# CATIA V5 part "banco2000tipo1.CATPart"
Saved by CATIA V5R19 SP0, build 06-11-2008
Part number: banco2000tipo1
Material "Pine": density 500 kg/m3, Young's modulus 1.7e+10 Pa, Poisson ratio 0.45, thermal expansion 3.75e-06 1/K
Bounding box of the stored display mesh (mm): x -1000 to 1000, y -375 to 375, z -880 to 40
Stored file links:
  C:\Users\Fran Robles\Desktop\Clase de Catia\banco2000tipo1.CATPart
  C:\Program Files\Dassault Systemes\B19\win_b64\startup\materials\Catalog.CATMaterial
  C:\Program Files\Dassault Systemes\B19\win_b64\startup\materials\pinetree.jpg
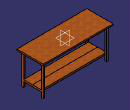
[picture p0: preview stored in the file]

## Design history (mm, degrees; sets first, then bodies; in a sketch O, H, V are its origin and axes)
Parameters
  Longitud_encimera = 2000 mm
  Ancho_encimera = 750 mm
  Altura_banco = 920 mm
  Altura_bandeja = 140 mm
  Altura_bandeja_porcentual_altura_banco = 0.25
Body1 (main body), material "Pine"
  Sketch1 "Encimera" on xy-plane, origin (0, 0, 0), H (1, 0, 0), V (0, 1, 0)
    line L1 (1000, 375) -> (1000, -375)
    line L2 (1000, -375) -> (-1000, -375)
    line L3 (-1000, -375) -> (-1000, 375)
    line L4 (-1000, 375) -> (1000, 375)
    length L2 = 2000 {= Longitud_encimera}
    length L1 = 750 {= Ancho_encimera}
    vertical: L1 V, L3 V
    horizontal: L2 H, L4 H
    equidistance: L1 L3 O, L2 L4 O
  Pad1: profile Sketch1, direction (0, 0, 1), length 40
  Sketch2 "Soporte de encimera" on start face of Pad1, origin (0, 0, 0), H (1, 0, 0), V (0, -1, 0)
    line L1 (930, 305) -> (930, -305)
    line L2 (930, -305) -> (-930, -305)
    line L3 (-930, -305) -> (-930, 305)
    line L4 (-930, 305) -> (930, 305)
    reference projected line E1 (-1000, 375) -> (1000, 375) from edge [start face of Pad1 | face of Pad1 from Sketch1.L2]
    reference projected line E2 (1000, 375) -> (1000, -375) from edge [start face of Pad1 | face of Pad1 from Sketch1.L1]
    line L5 (890, 265) -> (890, -265)
    line L6 (890, -265) -> (-890, -265)
    line L7 (-890, -265) -> (-890, 265)
    line L8 (-890, 265) -> (890, 265)
    distance E1 L4 = 70
    distance L1 E2 = 70
    distance L8 L4 = 40
    distance L5 L1 = 40
    vertical: L1 V, L3 V, L5 V, L7 V
    horizontal: L2 H, L4 H, L6 H, L8 H
    equidistance: L1 L3 O, L2 L4 O, L5 L7 O, L6 L8 O
  Pad2: profile Sketch2, direction (0, 0, -1), length 50
  Sketch3 "Pie de banco" on face of Pad2 from Sketch2.L3, origin (-930, 0, 0), H (0, -1, 0), V (0, 0, 1)
    reference projected line E1 (-375, 40) -> (375, 40) from edge [face of Pad1 from Sketch1.L3 | end face of Pad1]
    reference projected line E2 (305, -50) -> (-305, -50) from edge [face of Pad2 from Sketch2.L3 | end face of Pad2]
    point P3 (305, -50)
    line L1 (305, -50) -> (305, -880)
    point P5 (305, -880)
    line L2 (305, -880) -> (255, -880)
    point P6 (255, -880)
    line L3 (255, -880) -> (255, -740)
    point P7 (255, -740)
    line L4 (255, -740) -> (0, -740)
    point P8 (0, -740)
    construction line L5 (0, -740) -> (0, -690)
    point P9 (0, -690)
    line L6 (0, -690) -> (255, -690)
    point P10 (255, -690)
    line L7 (255, -690) -> (255, -50)
    point P11 (255, -50)
    line L8 (255, -50) -> (305, -50)
    point P12 (-255, -50)
    point P13 (-255, -690)
    line L9 (-255, -690) -> (-255, -50)
    point P14 (-305, -50)
    line L10 (-255, -50) -> (-305, -50)
    point P15 (-305, -880)
    line L11 (-305, -50) -> (-305, -880)
    point P16 (-255, -880)
    line L12 (-305, -880) -> (-255, -880)
    point P17 (-255, -740)
    line L13 (-255, -880) -> (-255, -740)
    point P18 (0, -740)
    line L14 (-255, -740) -> (0, -740)
    point P19 (0, -690)
    line L15 (0, -690) -> (-255, -690)
    distance L2 E1 = 920 {= Altura_banco}
    distance L3 L1 = 50
    distance L4 L6 = 50
    distance L2 L4 = 140 {= Altura_bandeja}
    vertical: L1 V, L3 V, L5 V, L7 V
    horizontal: L2 H, L4 H, L6 H, L8 H
    coincidence: P8 V, P10 L3, P11 E2, P8 P18, P9 P19
    symmetry: P11 P12 V, P10 P13 V, L7 L9 V, P3 P14 V, L8 L10 V, P5 P15 V, L1 L11 V, P6 P16 V, L2 L12 V, P7 P17 V, L3 L13 V, P8 P18 V, L4 L14 V, P9 P19 V, L6 L15 V
  Pad3: profile Sketch3, direction (1, 0, 0), length 40
  Mirror1: of Pad3, about yz-plane
  Sketch4 "Bandeja" on face of Pad3, origin (-890, 0, 0), H (0, 1, 0), V (0, 0, 1)
    line L1 (0, -740) -> (255, -740)
    line L2 (255, -740) -> (255, -690)
    line L3 (255, -690) -> (0, -690)
    line L4 (0, -690) -> (-255, -690)
    line L5 (-255, -690) -> (-255, -740)
    line L6 (-255, -740) -> (0, -740)
    horizontal: L1 H, L3 H, L4 H, L6 H
    vertical: L2 V, L5 V
  Pad4: profile Sketch4, direction (1, 0, 0), up to the existing solid (limit type 2)
Relations
  Ancho_encimera = Ancho_encimera (deactivated)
